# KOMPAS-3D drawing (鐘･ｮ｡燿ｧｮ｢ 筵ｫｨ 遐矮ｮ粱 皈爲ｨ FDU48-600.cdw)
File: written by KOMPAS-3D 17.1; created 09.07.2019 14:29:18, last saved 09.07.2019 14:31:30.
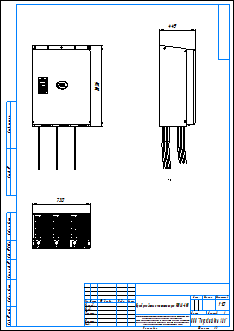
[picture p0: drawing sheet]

Sheet 1: A3, portrait

Title block, sheet 1: name: Преобразователи частоты серии FDU48-600; sheets: 1; sheet format: A3; stored path: \\adlc.lan\data\АДЛ_ПКД\3D-модели\Поставщики\Оборудование Emotron\Преобразователи частоты\Серия FDU 2.0\KOMPAS 2D\Преобразователи частоты серии FDU48-600.cdw

Views: Вид 1
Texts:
  user
  CONTINUOUS_RGB_0_0_0_THICK_0.18
  POLYLINE_STYLE_0.18_RGB_0_0_0
  Рама для чертежей
  Лит-Масса-Масштаб
  Материал-Предприятие
  Масштаб
  Изм.
  Лист
  № докум.
  Подп.
  Дата
  Лит.
  Разраб.
  Пров.
  Т.контр.
  Листов
  Внимание! Данный продукт является объектом авторского права ООО «Торговый Дом АДЛ».
  Запрещается изменение, копирование, распространение
  (в том числе путем копирования на другие сайты и ресурсы в Интернете)
  или любое иное использование информации и объектов без предварительного
  согласия правообладателя (ООО «Торговый Дом АДЛ»).
  Н.контр.
  Утв.
  ООО "Торговый дом АДЛ"
  Изменение
  Номер документа
  Подпись
  Обозначение документа
  Наименование изделия
  Масса изделия по ГОСТ 2.109-73
  Порядковый номер листа
  Общее количество листов в документе
  Характер работы, выполненной лицом, подписавшим документ
  Наименование или индекс предприятия, выпускающего документ
  Инв. № подл.
  Подп. и дата
  Взам. инв. №
  Инв. № дубл.
  Инвентарный номер подлинника по ГОСТ 2.501-68
  Подпись принявшего подлинник в отдел технической документации
  Инвентарный номер подлинника, взамен которого выпущен данный подлинник
  Инвентарный номер дубликата по ГОСТ 2.502-68
  Подпись принявшего дубликат в отдел технической документации
  Справ. №
  Перв. примен.
  Обозначение документа, взамен или на основании которого выпущен данный документ
  Обозначение документа, в котором впервые записан данный документ
  Подпись лица, копировавшего чертеж
  Обозначение формата листа
  !Рама для чертежа
Dimensions and other numbers on the sheet: 730; 449; 1036; 1:10; 1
